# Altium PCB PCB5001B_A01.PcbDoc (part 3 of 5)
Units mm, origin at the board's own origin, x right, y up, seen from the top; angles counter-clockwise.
Board outline 115 x 60 mm, 6 copper layers (Top Layer, GND Layer 2, Signal Layer 3, Signal Layer 4, VCC Layer 5, Bottom Layer), stack 1.555 mm thick; 370 components, 274 nets, 1305 pads, 1129 vias.
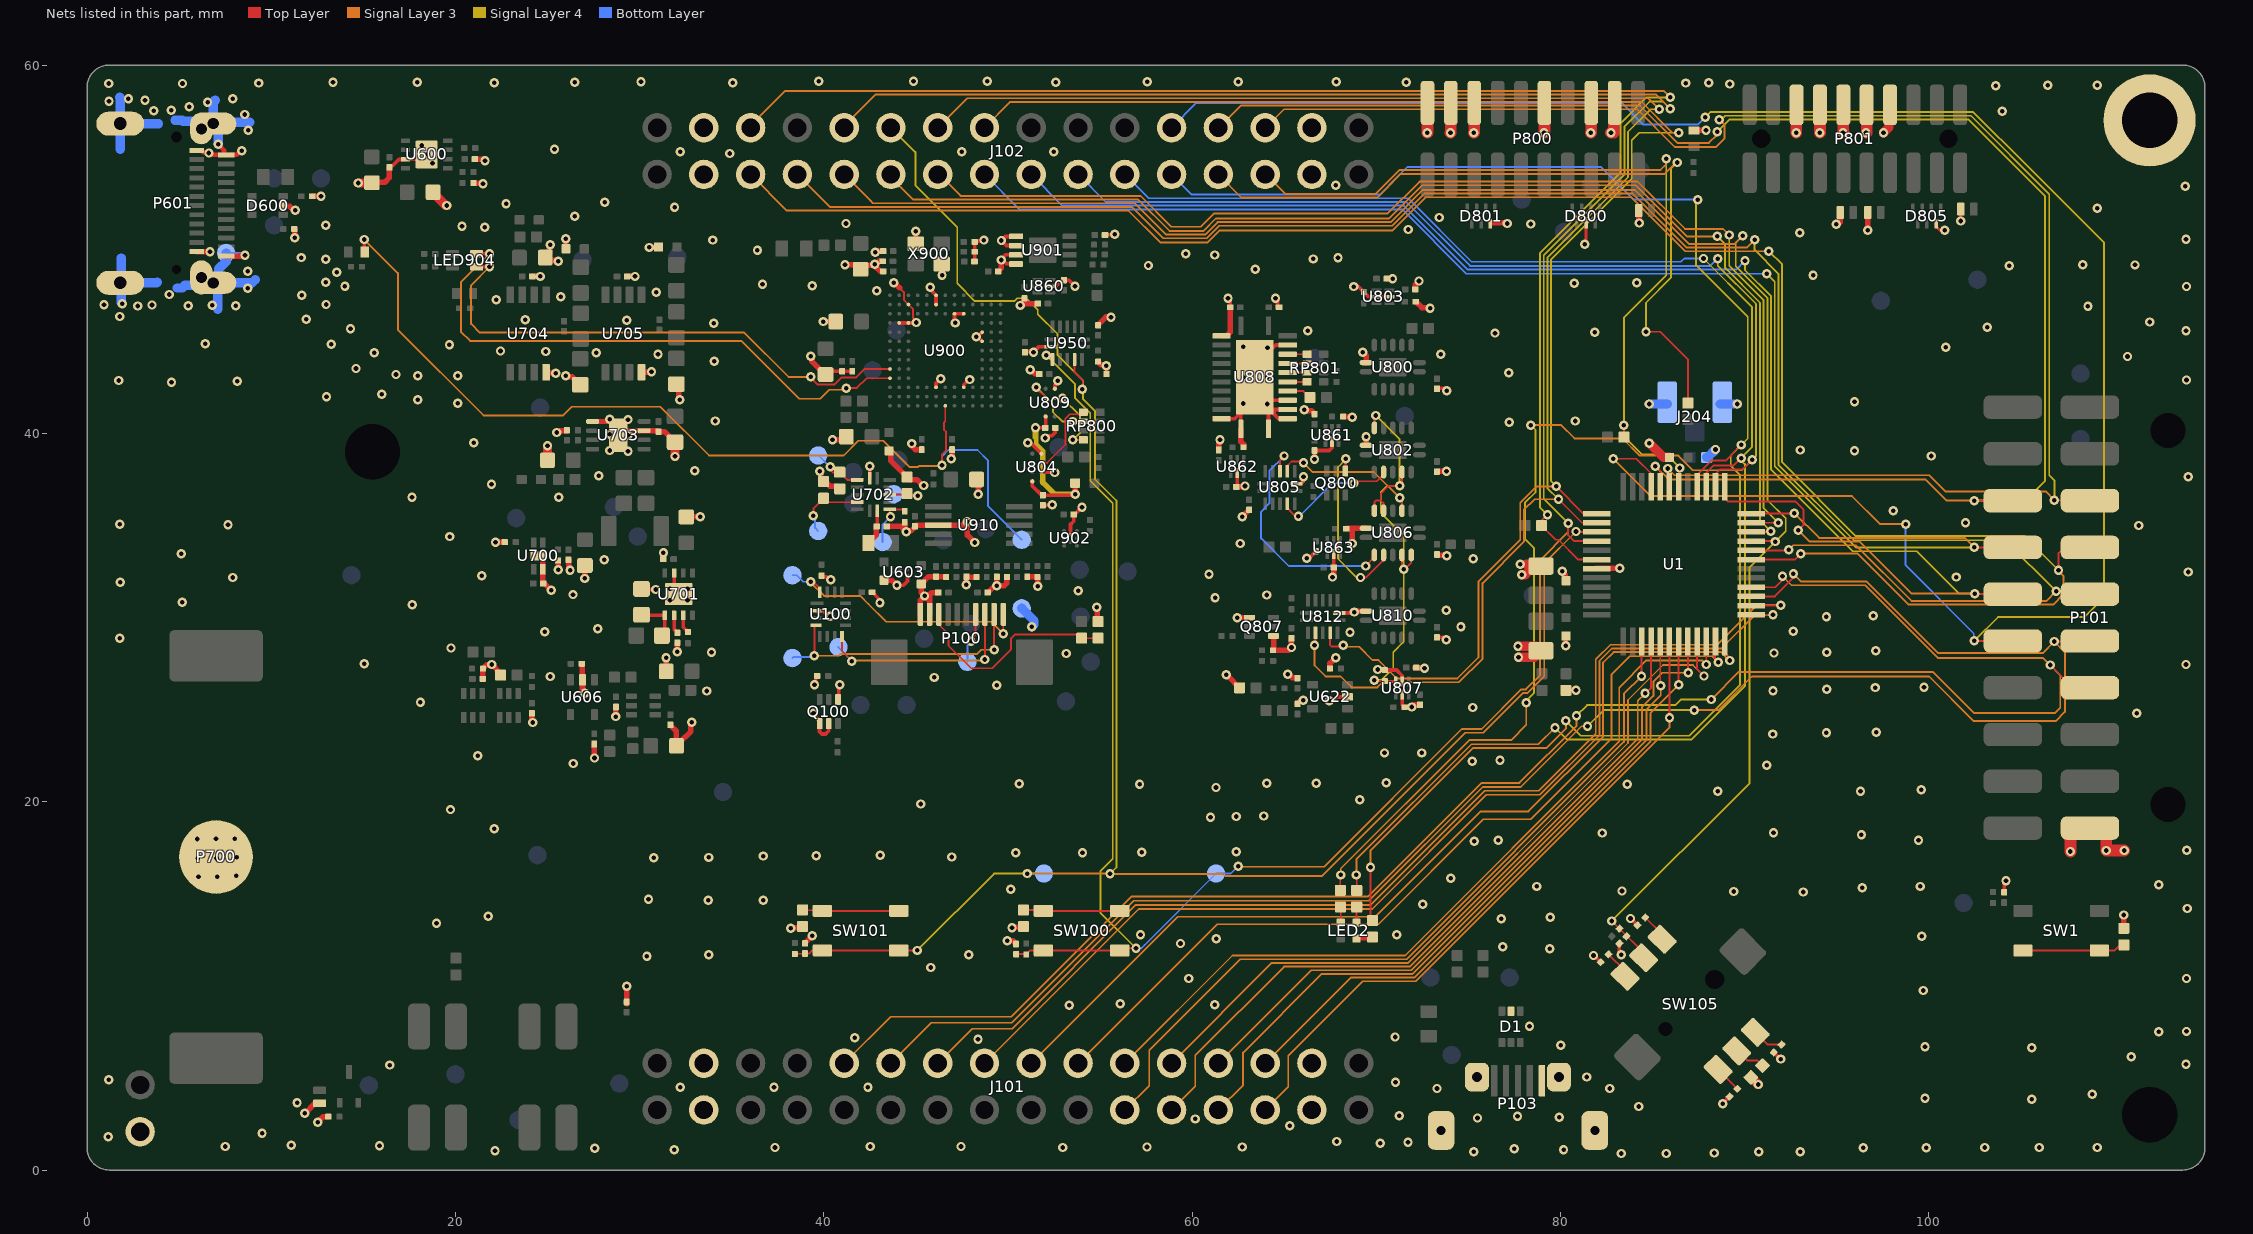
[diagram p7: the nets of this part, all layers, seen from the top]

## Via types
v1: diameter 0.508, hole 0.25, Top Layer to Bottom Layer, tented both sides, 1129 vias

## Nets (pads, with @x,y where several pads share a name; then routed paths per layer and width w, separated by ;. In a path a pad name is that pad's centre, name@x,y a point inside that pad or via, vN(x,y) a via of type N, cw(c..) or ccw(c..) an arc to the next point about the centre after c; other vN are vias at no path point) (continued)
EXP_HEADER7: J101.10 P101.7 U1.28 | length 100
  Top Layer w0.1: U1.28@90.375,31.65 91.677,31.65 92.075,32.048 92.075,32.247 v1(92.063,32.247) ; v1(106.6,27.425) 107.835,26.19 P101.7@108.76,26.19
  Signal Layer 3 w0.1: J101.10@41.11,5.802 41.128,5.82 43.633,8.325 50.175,8.325 56.7,14.85 69.55,14.85 75.725,21.025 77.775,21.025 80.879,24.129 80.879,24.671 v1(80.875,24.675) ; v1(88.2,25.55) 89.7,27.05 100.225,27.05 102.45,24.825 106.875,24.825 107.15,25.1 107.15,26.875 v1(106.6,27.425) 106.225,27.8 100.509,27.8 96.552,31.757 92.553,31.757 v1(92.063,32.247)
  Signal Layer 4 w0.1: v1(80.875,24.675) 81.45,25.25 86.25,25.25 86.55,25.55 v1(88.2,25.55)
EXP_HEADER9: J101.12 P101.9 U1.27 | length 98.8
  Top Layer w0.1: U1.27@90.375,31.15 91.65,31.15 92.657,32.157 v1(92.657,32.375) ; v1(106.825,28.7) 108.73,28.7 P101.9@108.76,28.73
  Signal Layer 3 w0.1: J101.12@43.65,5.802 45.848,8 50.2,8 56.825,14.625 69.608,14.625 75.783,20.8 77.85,20.8 81.15,24.1 v1(81.475,24.1) ; v1(87.275,24.975) 88.575,24.975 90.4,26.8 100.025,26.8 102.45,24.375 106.9,24.375 107.4,24.875 107.4,28.125 v1(106.825,28.7) 106.2,28.075 100.517,28.075 96.635,31.957 93.075,31.957 v1(92.657,32.375)
  Signal Layer 4 w0.1: v1(81.475,24.1) 82.35,24.975 v1(87.275,24.975)
EXP_HEADER10: J102.24 P101.10 U1.45 | length 112.6
  Top Layer w0.1: v1(82.875,38.625) 84.125,38.625 84.925,37.825 U1.45@84.925,37.1 ; v1(102.482,28.733) 104.567,28.733 P101.10@104.57,28.73
  Signal Layer 3 w0.1: v1(82.875,38.625) 84.9,36.6 95.837,36.6 97.362,35.075 v1(98.75,35.075)
  Signal Layer 4 w0.1: v1(87.875,57.175) 88.15,57.45 102.425,57.45 105.35,54.525 109.525,50.35 109.525,31.1 108.45,30.025 103.765,30.025 102.482,28.742 v1(102.482,28.733)
  Bottom Layer w0.1: J102.24@58.89,56.602 60.238,57.95 83.325,57.95 84.506,56.769 87.469,56.769 v1(87.875,57.175) ; v1(98.75,35.075) 98.75,32.838 102.452,29.137 102.452,28.763 v1(102.482,28.733)
EXP_HEADER11: J102.7 P101.11 U1.32 | length 106.5
  Top Layer w0.1: U1.32@90.375,33.65 92.375,33.65 v1(92.4,33.675) ; v1(106.919,31.424) 108.606,31.424 P101.11@108.76,31.27
  Signal Layer 3 w0.1: J102.7@38.57,54.062 40.332,52.3 56.725,52.3 58.425,50.6 60.792,50.6 61.467,51.275 70.867,51.275 72.617,53.025 83.932,53.025 86.864,50.093 90.118,50.093 v1(90.55,50.525) ; v1(92.4,33.675) 92.65,33.925 96.05,33.925 99.068,30.907 106.401,30.907 v1@106.912,31.418
  Signal Layer 4 w0.1: v1(90.55,50.525) 90.55,49.966 91.841,48.675 91.841,38.309 95.947,34.203 104.14,34.203 v1(106.919,31.424)
EXP_HEADER12: J102.17 P101.12 U1.37 | length 86.5
  Top Layer w0.1: U1.37@88.925,37.1 88.925,36.5 89.125,36.3 92.775,36.3 93.2,35.875 93.2,35.025 v1(92.925,34.75) ; v1(102.5,31.3) 102.526,31.274 104.566,31.274 P101.12@104.57,31.27
  Signal Layer 3 w0.1: v1(92.925,34.75) 93.55,34.125 96.25,34.125 99.075,31.3 v1(102.5,31.3)
  Signal Layer 4 w0.1: v1(90.025,49.375) 90.025,48.875 91.441,47.459 91.441,38.034 95.875,33.6 99.35,33.6 101.65,31.3 v1(102.5,31.3) v1@102.4,31.4
  Bottom Layer w0.1: J102.17@51.27,54.062 52.964,52.368 71.507,52.368 74.975,48.9 89.55,48.9 v1(90.025,49.375)
EXP_HEADER13: J102.5 P101.13 U1.31 | length 111
  Top Layer w0.1: U1.31@90.375,33.15 92.725,33.15 v1(93.05,33.475) ; v1(107.05,32.575) 107.05,33.5 107.41,33.86 P101.13@108.8,33.86
  Signal Layer 3 w0.1: J102.5@36.03,54.062 37.992,52.1 56.55,52.1 58.275,50.375 60.85,50.375 61.5,51.025 70.9,51.025 72.7,52.825 83.85,52.825 86.782,49.893 91.318,49.893 v1(91.325,49.9) ; v1(93.05,33.475) 96.15,33.475 98.918,30.707 106.757,30.707 107.318,31.268 107.318,32.272 107.05,32.539 v1(107.05,32.575)
  Signal Layer 4 w0.1: v1(91.325,49.9) 92.041,49.184 92.041,38.434 96.05,34.425 105.2,34.425 v1(107.05,32.575)
EXP_HEADER14: J102.15 P101.14 U1.36 | length 83
  Top Layer w0.1: U1.36@90.375,35.65 92.675,35.65 v1(92.7,35.675) ; v1(102.47,33.81) P101.14@104.57,33.81
  Signal Layer 3 w0.1: J102.15@48.73,54.062 J102.15@48.756,54.062 ; v1(92.7,35.675) 94.05,34.325 101.955,34.325 v1(102.47,33.81)
  Signal Layer 4 w0.1: v1(91.212,48.663) 91.641,48.234 91.641,38.209 96.04,33.81 v1(102.47,33.81)
  Bottom Layer w0.1: J102.15@48.73,54.062 50.624,52.168 71.407,52.168 74.9,48.675 91.2,48.675 v1(91.212,48.663)
EXP_HEADER15: J102.28 P101.15 U1.43 | length 88.8
  Top Layer w0.1: v1(85.835,38.096) 85.835,37.19 U1.43@85.925,37.1 ; v1(106.825,36.375) 107.941,36.375 107.966,36.4 P101.15@108.8,36.4
  Signal Layer 3 w0.1: J102.28@63.97,56.602 63.996,56.602 64.994,57.6 84.175,57.6 86.225,55.55 88.45,55.55 88.918,56.018 88.918,56.751 v1(88.631,57.037) ; v1(85.835,38.096) 85.835,38.09 86.2,37.725 100.025,37.725 100.9,36.85 106.35,36.85 v1(106.825,36.375)
  Signal Layer 4 w0.1: v1(88.631,57.037) 88.742,57.037 88.955,57.25 102.3,57.25 106.55,53 106.55,45.767 106.55,37.725 106.825,37.45 v1(106.825,36.375)
EXP_HEADER16: J102.26 P101.16 U1.44 | length 89.8
  Top Layer w0.1: v1(85.15,38.225) 85.169,38.225 85.425,37.969 U1.44@85.425,37.1 ; v1(102.47,36.35) P101.16@104.57,36.35
  Signal Layer 3 w0.1: J102.26@61.43,56.602 61.456,56.602 62.654,57.8 84.325,57.8 86.35,55.775 88.069,55.775 88.525,56.231 v1(88.525,56.375) ; v1(85.15,38.225) 85.875,37.5 99.825,37.5 100.975,36.35 v1(102.47,36.35)
  Signal Layer 4 w0.1: v1(88.525,56.375) 89.2,57.05 102.15,57.05 106.325,52.875 106.325,37.425 105.25,36.35 v1(102.47,36.35)
GND: C1.2 C2.2 C3.2 C4.2 C8.2 C102.2 C103.2 C104.2 C106.2 C113.2 C143.2 C144.2 C600.2 C602.2 C607.2 C608.2 C609.2 C610.2 C611.2 C621.2 C625.2 C632.2 C635.2 C638.2 C641.2 C652.2 C653.2 C655.2 C660.2 C673.2 C674.2 C700.2 C701.2 C702.2 C703.2 C705.2 C706.2 C707.2 C708.2 C714.2 C720.2 C724.2 C728.2 C729.2 C730.2 C731.2 C732.2 C800.2 C803.2 C804.2 C805.2 C806.2 C807.2 C808.2 C809.2 C810.2 C827.2 C828.2 C860.2 C861.2 C862.2 C863.2 C864.2 C865.2 C866.2 C867.2 C868.2 C869.2 C870.2 C900.2 C901.2 C902.2 C903.2 C904.2 C905.2 C906.2 C907.2 C908.2 C909.2 C910.2 C911.2 C914.2 C921.2 C922.2 C924.2 C925.2 C926.2 C927.2 C950.2 C951.2 D1.2 D600.2 D703.2 D800.6 D801.7 D805.7 D806.2 D807.2 D808.2 D809.2 J101.3 J101.4 J101.29 J101.30 J102.3 J102.4 J102.29 J102.30 J204.2 J204.3 LED900.2 M1.1 P100.1 P100.2 P101.1 P103.5 P103.6 P103.7 P103.8 P103.9 P601.25@1.8,56.82 P601.26@1.8,48.18 P601.27@6.2,56.525 P601.27@6.85,56.82 P601.28@6.2,48.475 P601.28@6.85,48.18 P601.A1 P601.A12 P601.B1 P601.B12 P700.2 P800.3 P800.5 P800.9 P800.15 P800.17 P800.19 P801.7 P801.9 P801.11 P801.13 P801.15 Q100.1 Q100.4 Q100.5 Q807.1 Q807.4 R7.1 R104.2 R105.2 R113.1 R121.1 R124.1 R125.1 R126.1 R127.1 R140.1 R141.1 R146.1 R220.1 R602.1 R620.1 R621.1 R623.1 R628.2 R631.1 R634.1 R637.1 R640.1 R674.2 R688.2 R691.2 R703.1 R705.1 R706.1 R707.1 R708.1 R718.1 R760.1 R763.1 R767.1 R771.1 R792.1 R807.2 R808.2 R814.1 R817.1 R839.1 R850.1 R851.1 R852.1 R853.1 R930.2 R931.2 R950.2 R981.2 ST701.1 TPJ614.1 TPJ913.1 U1.7 U100.2 U600.3 U600.9 U603.A1 U606.2 U622.2 U700.2 U700.5 U701.3 U701.9 U702.7 U703.3 U703.5 U703.9 U704.4 U705.4 U800.7 U802.7 U803.2 U803.5 U804.B1 U804.D1 U805.7 U806.7 U807.2 U807.5 U808.2 U808.11 U808.12 U808.13 U808.14 U808.15 U808.16 U808.22 U808.25 U809.D1 U810.7 U812.7 U860.2 U861.2 U862.2 U863.2 U900.C5 U900.C8 U900.H3 U900.J3 U900.K11 U900.K12 U900.L5 U900.L6 U900.M8 U900.M11 U900.N8 U901.1 U901.2 U901.3 U901.4 U902.B2 U910.3 U950.7 X900.2 X900.4 | length 231.2
  Top Layer w0.1: 44.125,47.9 44.35,47.675 44.35,47.25 U900.M11@44.6,47 44.788,46.813 44.85,46.75 44.85,46.275 v1@45.025,46.1
  Top Layer w0.15: v1(81.325,50.275) 81.4,50.35 D800.6@81.4,51.385 ; D805.7@100.4,51.385 100.4,51.25 100.6,51.05 v1@101.05,51.05
  Top Layer w0.2: C600.2@16.417,54.451 16.417,54.471 16.477,54.531 16.581,54.531 16.922,54.872 17.257,54.872 U600.3@17.282,54.897 U600.9@18.182,54.897 ; R703.1@30.105,31.556 30.135,31.525 v1(30.875,31.525) ; U701.9@31.725,31.575 31.875,31.725 U701.3@31.875,32.425 ; v1(39.446,24.8) 39.446,24.719 39.775,24.39 Q100.4@39.775,24.24 39.775,23.8 39.9,23.675 40.1,23.675 40.275,23.85 Q100.5@40.275,24.24 ; v1(39.498,26.353) 39.498,26.437 39.572,26.511 39.572,26.772 39.632,26.832 R141.1@39.642,26.832 ; U100.2@39.59,30.375 39.956,30.375 40.261,30.07 v1(40.344,30.07) ; R140.1@39.888,32.275 39.888,32.265 39.948,32.205 40.158,32.205 40.307,32.057 v1(40.39,32.057) ; C907.2@40.1,43.2 40.275,43.375 C924.2@41,43.375 C925.2@41.55,43.375 ; Q100.1@40.775,25.54 40.818,25.583 40.818,26.306 v1(40.862,26.35) ; U702.7@42.5,37.56 v1(42.5,38.225) v1@42.65,38.225 ; C104.2@42.623,31.374 42.643,31.374 42.993,31.024 42.993,30.863 v1(43.052,30.804) ; v1(43.975,31.75) 44.325,31.75 44.55,31.975 U603.A1@44.55,32.25 ; U900.K12@44.1,46 U900.K11@44.6,46 45,46 v1(45.025,46.025) v1@45.025,46.1 ; v1@45.35,37.1 v1(45.425,37.175) ; v1(45.793,47.935) 45.793,47.802 46.095,47.5 U900.N8@46.1,47.5 U900.M8@46.1,47 ; U900.C8@46.1,42.5 46.1,42.725 v1(46.35,42.975) ; v1(47.15,46) 47.1,46.05 U900.L6@47.1,46.5 U900.L5@47.6,46.5 ; U900.C5@47.6,42.5 47.6,42.65 v1@47.875,42.925 ; C910.2@48.184,49.333 48.193,49.342 48.193,49.857 R930.2@48.201,49.865 ; R930.2@48.202,49.863 R930.2@48.201,49.865 ; v1@48.224,45.25 v1(48.275,45.25) 48.3,45.25 v1@48.325,45.275 ; U900.H3@48.6,45 v1@48.325,45.275 ; U900.J3@48.6,45.5 48.375,45.275 v1@48.325,45.275 ; v1(48.7,50.5) 48.65,50.45 48.25,50.45 R931.2@48.2,50.4 48.201,50.399 R930.2@48.201,49.865 ; v1@49.65,49.4 49.733,49.4 49.923,49.21 50.434,49.21 U901.4@50.445,49.2 ; v1@49.65,49.483 49.867,49.7 U901.3@50.445,49.7 ; U901.2@50.445,50.2 50.436,50.208 49.917,50.208 v1(49.65,50.475) 49.867,50.692 50.436,50.692 U901.1@50.445,50.7 ; C911.2@50.925,44.4 50.95,44.375 50.993,44.375 51.068,44.45 51.355,44.45 v1(51.392,44.413) ; v1@51.225,39.45 51.275,39.45 U804.D1@51.825,38.9 ; v1@51.4,44.45 51.413,44.45 51.663,44.7 U950.7@52.34,44.7 ; U804.B1@51.825,37.9 52.525,37.9 v1(52.55,37.875) ; C804.2@51.9,36.1 52.375,36.1 v1(52.4,36.125) ; v1(52.025,39.75) 52.15,39.875 52.4,39.875 52.575,40.05 C810.2@52.575,40.3 ; U860.2@52.3,48 52.625,48 52.95,48.325 C862.2@53.05,48.325 53.309,48.325 v1(53.645,47.989) ; U809.D1@52.55,42.425 52.556,42.431 52.556,42.63 52.709,42.784 v1(52.709,42.867) ; C862.2@53.05,48.305 C862.2@53.11,48.245 ; U902.B2@53.4,34.5 53.4,35.05 53.575,35.225 C914.2@53.575,35.55 ; C914.2@53.575,35.6 C914.2@53.575,35.55 ; v1(54.025,36) C914.2@53.575,35.55 ; C951.2@55.272,50.778 55.29,50.796 55.787,50.796 v1(55.805,50.814) ; R981.2@55.35,43.225 v1(55.35,43.679) ; U808.11@61.605,40.8 62.325,40.8 U808.25@62.65,41.125 ; v1(61.95,47.35) 62.075,47.225 C808.2@62.075,46.85 ; C860.2@62.4,37.1 62.45,37.15 U862.2@62.45,37.85 ; U808.12@62.65,40.255 U808.25@62.65,41.125 ; v1(62.775,41.625) 62.775,41.25 U808.25@62.65,41.125 ; v1(64.1,44.65) 64.4,44.65 64.55,44.8 U808.22@65.195,44.8 ; U808.13@64.15,40.255 64.15,41.3 64.2,41.3 64.45,41.05 ; v1(64.532,47.345) 64.532,47.275 64.645,47.162 64.645,46.91 64.705,46.85 C806.2@64.725,46.85 ; U808.14@65.195,40.8 64.7,40.8 64.45,41.05 ; U808.15@65.195,41.3 U808.25@64.375,41.3 ; U808.16@65.195,41.8 64.275,41.8 v1(64.075,41.6) U808.25@64.375,41.3 ; U805.7@65.66,37.27 65.92,37.27 66.025,37.375 66.025,37.625 v1(66.05,37.65) ; v1(66.225,33.225) 66.35,33.225 C867.2@66.725,33.6 ; v1(66.65,38.6) C864.2@66.65,39.075 67.45,39.075 67.6,39.225 U861.2@67.6,39.55 ; v1(67.45,25.475) 67.643,25.475 67.859,25.691 68.441,25.691 U622.2@68.45,25.7 ; C866.2@67.7,32.725 U863.2@67.7,33.45 ; U812.7@67.985,30.25 68.75,30.25 v1(68.8,30.3) ; C827.2@73.3,28.925 73.675,28.925 v1(73.8,28.8) ; C803.2@73.325,42.45 73.7,42.45 v1(73.825,42.325) ; v1@73.802,37.938 v1(73.816,37.951) ; v1(81.8,11.65) 81.826,11.65 R124.1@82.188,11.288 ; C106.2@83.206,12.306 83.206,11.794 v1(83.3,11.7) ; v1(83.807,13.657) 83.833,13.657 R127.1@84.195,13.295 ; v1(88.826,3.6) 88.826,3.626 R125.1@89.188,3.988 ; R126.1@91.588,6.388 91.95,6.026 v1(91.976,6.026) ; v1@101.749,51.534 D808.2@101.748,52.181 ; C8.2@104.1,15.075 104.1,15.6 v1(104.2,15.7) ; U808.25@64.375,41.3 64.45,41.225 64.45,41.05
  Top Layer w0.203: v1(68.775,47.975) 69.025,47.975 R807.2@69.325,47.675 69.575,47.425 U803.2@70.025,47.425 U803.5@70.725,47.425 ; v1(70.077,27.182) 70.093,27.166 70.459,27.166 R808.2@70.475,27.15 71.1,27.15 71.413,26.837 U807.2@71.413,26.525 ; U807.5@71.413,25.825 71.413,25.249 R814.1@71.532,25.13
  Top Layer w0.25: P601.B12@5.95,55.375 5.96,55.365 6.225,55.365 6.313,55.277 6.566,55.277 v1(6.615,55.227) ; v1@6.658,55.178 6.735,55.178 6.777,55.135 P601.A1@7.432,55.135 ; v1(7.128,55.71) 7.128,55.689 7.432,55.385 P601.A1@7.432,55.135 ; v1(8.398,55.347) 8.328,55.347 8.116,55.135 7.56,55.135 P601.A1@7.55,55.125 ; U703.5@27.45,40.65 v1@28.25,40.65 ; P601.A1@7.432,55.135 7.54,55.135 P601.A1@7.55,55.125 ; P601.A1@7.432,55.135 7.442,55.125 P601.A1@7.55,55.125
  Top Layer w0.254: v1(80.1,32.525) 80.3,32.325 C2.2@80.3,32 ; v1(80.3,28.475) C4.2@80.3,29
  Top Layer w0.3: P601.B1@5.95,49.875 v1(6.675,49.875) ; P601.A12@7.55,49.625 8.25,49.625 8.26,49.635 8.535,49.635 v1(8.575,49.675) ; D600.2@10.647,52.374 10.684,52.336 10.993,52.336 11.207,52.122 v1(11.298,52.122) ; R621.1@11.25,51.1 11.252,51.1 11.262,51.09 11.262,50.637 v1(11.275,50.625) ; R620.1@12.224,52.88 12.226,52.878 12.697,52.878 v1(12.7,52.875) ; C611.2@15.525,53.55 15.614,53.639 16.164,53.639 16.417,53.892 C600.2@16.417,54.451 ; R602.1@20.982,53.597 20.982,53.587 20.992,53.577 21.472,53.577 v1(21.498,53.552) ; C602.2@21.057,54.897 21.507,54.897 v1(21.607,54.797) ; C610.2@21.475,26.675 21.475,27.2 R623.1@21.5,27.225 21.725,27.45 v1(21.975,27.45) 22.45,26.975 R628.2@22.45,26.875 ; v1(22.175,34.1) v1(22.175,34.1) 22.678,34.099 R763.1@22.679,34.098 ; C621.2@24.15,24.8 24.15,24.35 v1(24.2,24.3) ; U700.5@24.5,33.35 24.65,33.35 24.75,33.25 U700.2@24.75,32.625 24.75,31.875 C708.2@24.775,31.85 24.825,31.85 v1(25.2,31.475) ; v1(25.5,40.05) 25.556,40.05 25.651,40.145 26.04,40.145 26.05,40.155 C728.2@26.05,40.175 ; R760.1@25.573,33.103 R760.1@25.573,33.103 v1(25.575,32.6) v1(25.575,32.6) ; C701.2@26.134,33.137 26.144,33.127 26.144,32.713 26.225,32.631 v1(26.225,32.575) ; R674.2@26.86,27.49 26.87,27.49 26.88,27.48 26.88,26.645 U606.2@26.9,26.625 26.9,26.025 v1(27.025,25.9) ; v1(27.025,32.125) 27.029,32.129 27.029,32.821 C700.2@27.033,32.825 ; C660.2@27.537,23.135 27.544,23.128 27.544,22.381 v1(27.55,22.375) ; v1@28.25,40.65 v1(28.375,40.775) ; v1(28.7,24.625) 28.706,24.631 28.706,25.14 C674.2@28.713,25.147 ; U703.9@28.85,39.9 U703.9@29.1,40.15 ; v1(29.373,40.753) 29.334,40.713 29.334,40.65 29.2,40.65 29.1,40.55 U703.9@29.1,40.15 ; C702.2@31.295,33.171 v1(31.295,33.521) ; v1(31.438,27.822) 31.443,27.817 31.443,27.085 C625.2@31.448,27.08 ; C673.2@31.685,24.145 32.004,23.826 C655.2@32.004,23.061 ; R718.1@31.925,39.525 31.35,40.1 C729.2@31.025,40.1 30.975,40.15 U703.3@30.25,40.15 U703.9@29.1,40.15 ; C655.2@32.004,23.036 C655.2@32.004,23.061 ; v1(32.05,28.15) C705.2@32.05,28.629 ; C703.2@32.535,35.461 32.542,35.468 33.293,35.468 v1(33.3,35.475) ; v1(32.826,24.318) 32.787,24.278 32.787,23.819 32.493,23.526 32.468,23.526 C655.2@32.004,23.061 ; v1@38.15,13.15 38.165,13.165 38.79,13.165 R105.2@38.85,13.225 ; v1(38.2,13.125) v1@38.225,13.15 ; C103.2@38.986,12.306 38.986,12.326 39.373,12.713 v1(39.382,12.713) ; v1(39.304,44.196) 39.343,44.156 39.343,43.932 40.075,43.2 C907.2@40.1,43.2 ; v1(39.793,37.95) 39.793,37.894 39.843,37.844 39.843,37.529 R705.1@39.993,37.379 ; v1(39.975,46.075) C900.2@40.65,46.075 ; R705.1@40.125,37.35 40.125,37.247 40.143,37.229 40.246,37.229 40.331,37.144 40.72,37.144 R706.1@40.87,36.994 ; v1(40.475,39.65) 41.05,39.65 C902.2@41.225,39.825 ; v1(41.156,49.165) 41.756,49.165 C903.2@42.006,48.915 ; C903.2@42.1,49 42.229,49.129 42.723,49.129 v1(42.777,49.183) ; v1(42.804,49.833) 42.861,49.833 42.914,49.886 43.213,49.886 C906.2@43.223,49.896 ; C905.2@43.21,49.352 43.2,49.342 42.992,49.342 42.834,49.183 v1(42.777,49.183) ; C904.2@43.223,48.802 43.213,48.812 43.057,48.812 42.817,49.052 42.817,49.143 v1(42.777,49.183) ; C609.2@43.275,32.025 43.7,32.025 v1(43.975,31.75) ; C707.2@43.425,34.95 44.193,34.95 v1@44.396,34.747 ; C901.2@43.55,39.05 43.65,38.95 43.65,38.512 R707.1@44.523,37.639 44.673,37.489 45.054,37.489 45.369,37.175 v1(45.425,37.175) ; v1(43.8,48.182) 43.843,48.182 44.125,47.9 ; R708.1@44.4,35.175 44.4,35.159 44.396,35.155 v1@44.396,34.747 ; v1(44.476,34.667) v1@44.396,34.747 ; v1@44.5,34.6 44.5,34.635 44.572,34.707 44.727,34.707 44.95,34.93 C922.2@44.95,34.95 ; v1(44.775,39.45) 44.775,39.325 44.975,39.125 C927.2@45.325,39.125 ; C922.2@44.94,34.94 C922.2@44.95,34.95 ; X900.4@45,50.3 v1(45,50.975) ; P100.1@45.25,30.175 45.25,30.95 v1(45.475,31.175) ; P100.2@45.75,30.175 45.75,30.9 ; C143.2@46.224,31.364 46.214,31.354 45.854,31.354 45.75,31.25 ; X900.2@46.4,49.2 46.4,48.6 46.421,48.579 v1(46.425,48.582) ; R637.1@46.65,32.2 46.625,32.225 C638.2@46.1,32.225 45.7,32.225 C608.2@45.3,31.825 45.3,31.35 v1(45.475,31.175) ; v1@46.975,38.625 C926.2@46.975,39.125 ; v1(47.742,31.782) v1@47.746,31.786 ; v1@47.782,31.822 v1@47.746,31.786 ; v1@47.825,35.225 v1(47.8,35.2) ; v1(48.2,34.075) 47.8,34.475 v1(47.8,35.2) ; R640.1@48.29,32.18 48.29,32.19 R640.1@48.3,32.2 47.775,32.2 C641.2@47.75,32.225 47.746,32.221 v1@47.746,31.786 ; C921.2@48.3,37.5 48.4,37.4 v1(48.4,36.7) ; C144.2@48.9,31.368 48.92,31.368 49.236,31.685 49.36,31.685 v1(49.4,31.725) ; C635.2@49.4,32.225 v1(49.4,31.725) ; C908.2@49.475,48.8 49.65,48.975 49.65,49.4 v1(49.634,49.416) ; R634.1@49.95,32.2 49.95,31.875 49.8,31.725 v1(49.4,31.725) ; v1(49.975,12.45) 50.275,12.45 C102.2@50.45,12.275 ; v1@50.225,13.125 50.285,13.185 50.812,13.185 R104.2@50.847,13.22 ; R850.1@50.9,47.342 50.89,47.332 50.89,47.221 50.675,47.006 v1(50.675,46.95) 50.731,46.95 50.831,47.05 C863.2@51.625,47.05 ; C632.2@51.05,32.225 51.575,32.225 R631.1@51.6,32.2 51.625,32.175 v1(51.625,31.7) ; v1(51.214,43.449) 51.27,43.449 51.484,43.234 51.695,43.234 C909.2@51.705,43.224 ; v1(54.834,30.559) 54.856,30.537 54.856,29.793 R146.1@54.877,29.772 ; R950.2@54.9,43.9 54.9,43.89 55.071,43.719 55.311,43.719 v1(55.35,43.679) ; C950.2@54.9,45.875 54.91,45.885 54.91,45.905 55.328,46.323 55.577,46.323 v1(55.6,46.3) ; C861.2@61.45,39.1 61.46,39.11 61.46,39.536 61.518,39.594 v1(61.518,39.65) ; U808.2@61.605,45.3 61.875,45.3 62.075,45.5 C808.2@62.075,46.85 ; v1(61.853,26.903) 61.975,26.903 61.975,26.789 R691.2@62.577,26.187 ; C860.2@62.4,37.1 62.773,37.1 62.819,37.145 v1(62.875,37.145) ; v1(62.45,30) Q807.4@63.125,30 ; U808.12@62.65,40.255 62.65,39.55 62.8,39.4 R852.1@62.8,39.25 ; v1(62.725,35.475) C800.2@63.1,35.85 ; Q807.1@64.425,29 64.425,28.25 R839.1@64.4,28.225 65.25,28.225 v1(65.4,28.375) C828.2@65.4,28.875 ; v1(65.2,26.921) 65.256,26.921 65.432,26.745 65.71,26.745 65.72,26.735 C653.2@65.72,26.715 ; C652.2@65.725,25.311 65.725,25.331 65.979,25.585 v1(66.048,25.516) ; v1(66.1,41.282) 66.138,41.244 66.476,41.244 C865.2@66.64,41.08 ; R688.2@67.486,27.233 67.486,27.511 v1(67.8,27.825) ; v1(67.625,32.2) 67.7,32.275 C866.2@67.7,32.725 ; R851.1@68.2,40.912 68.21,40.902 68.673,40.902 v1(68.7,40.875) ; R853.1@68.375,34.825 68.4,34.85 68.678,34.85 ; v1(68.7,34.025) 68.7,34.822 68.675,34.847 68.678,34.85 ; v1(68.8,30.3) 68.85,30.35 U810.7@69.45,30.35 ; v1(69.275,44.4) 69.45,44.225 U800.7@69.45,43.85 ; U806.7@69.45,34.85 68.678,34.85 ; U802.7@69.45,39.35 v1(69.45,39.825) ; C809.2@73.3,33.425 73.3,33.405 73.31,33.395 73.724,33.395 73.769,33.35 v1(73.825,33.35) ; C805.2@73.3,37.925 73.3,37.928 73.31,37.938 73.788,37.938 v1@73.811,37.961 ; v1(73.825,42.325) v1@73.881,42.325 ; D801.7@76.255,51.449 77.076,51.449 v1(77.125,51.4) ; D809.2@84.25,52.1 84.271,52.079 84.271,51.446 v1(84.293,51.425) ; LED900.2@87.25,56.45 87.26,56.46 87.898,56.46 v1(87.908,56.47) ; v1(94.975,51.35) 95.075,51.35 95.2,51.475 D806.2@95.2,52 ; v1(96.692,51.031) 96.696,51.035 96.696,51.996 D807.2@96.7,52 ; R7.1@110.6,13.125 v1(110.6,13.85) ; C922.2@44.95,34.95 45.025,35.025 U910.3@46.225,35.025 47.625,35.025 v1(47.8,35.2) ; v1(45.475,31.175) 45.55,31.25 45.75,31.25 ; v1(45.475,31.175) 45.75,30.9 ; 45.75,30.9 45.75,31.25
  Top Layer w0.305: v1(11.825,3.075) 12.375,3.625 D703.2@12.625,3.625 ; v1(12.525,2.6) 12.825,2.9 R792.1@13.1,2.9 ; C730.2@24.175,48.525 v1(24.6,48.525) ; C731.2@24.875,49.55 25.111,49.786 25.111,50.211 v1(25.15,50.25) ; C731.2@24.914,49.511 25.036,49.389 25.536,49.389 v1(25.575,49.35) ; U704.4@24.925,43.32 24.947,43.297 25.428,43.297 v1(25.45,43.275) ; v1(26,43.125) 26.039,43.086 26.314,43.086 26.75,42.65 R767.1@26.775,42.65 ; C720.2@26,50.025 v1(26,50.575) ; C706.2@29.3,9.025 v1(29.3,9.975) ; C732.2@29.325,48.525 v1(29.75,48.525) ; U705.4@30.1,43.32 30.62,43.32 v1(30.65,43.35) ; v1(30.525,50.1) 31,50.1 C724.2@31.025,50.125 ; R771.1@32,42.675 32.136,42.539 32.136,41.864 v1(32.175,41.825) ; C869.2@70.569,48.403 v1(70.889,48.403) ; R814.1@71.532,25.13 71.538,25.136 71.838,25.136 71.845,25.143 v1(71.932,25.143) ; v1@71.932,25.13 72.066,25.264 C868.2@72.376,25.264 ; C870.2@72.089,27.284 C870.2@72.175,27.284 72.591,27.284 v1(72.625,27.25) v1@72.601,27.226 ; C807.2@72.125,47.825 72.125,48.075 v1(72.325,48.275) ; R817.1@72.15,47.15 72.16,47.15 72.478,46.832 72.886,46.832 v1(72.925,46.793) ; R121.1@80.325,26.05 v1(80.85,26.05) ; U1.7@81.954,32.675 v1(83.225,32.675)
  Top Layer w0.5: v1(14.721,53.599) 14.722,53.601 15.451,53.601 C611.2@15.465,53.614 ; C607.2@18.782,53.097 18.782,53.072 19.478,52.377 19.523,52.377 v1(19.525,52.375) ; C714.2@25,38.55 v1(25,39.325) ; v1(31.925,38.75) R718.1@31.925,39.525 ; R113.1@90.342,5.037 90.351,5.037 90.743,4.645 v1(90.745,4.645) ; v1(97.55,56.325) 97.85,56.625 97.85,57.786 P801.7@97.905,57.841
  Top Layer w0.508: v1(77.7,28.45) 78.675,28.45 78.925,28.2 C3.2@78.95,28.2 78.6,27.85 v1(77.725,27.85) ; v1(77.9,32.325) 78.1,32.325 C1.2@78.375,32.6 ; 78.162,32.9 78.263,32.8 C1.2@78.95,32.8 ; v1(84.825,39.475) 85.6,38.7 C113.2@85.925,38.7
  Top Layer w0.635: v1(72.765,56.325) 72.785,56.345 P800.19@72.785,57.95 ; v1(74.035,56.325) 74.055,56.345 P800.17@74.055,57.95 ; v1(75.305,56.325) 75.325,56.345 P800.15@75.325,57.95 ; v1(79.115,56.325) 79.135,56.345 P800.9@79.135,57.95 ; v1(81.655,56.325) 81.675,56.345 P800.5@81.675,57.95 ; v1(82.75,56.325) 82.882,56.325 82.893,56.335 82.893,57.897 P800.3@82.945,57.95 ; v1(92.811,56.325) 92.811,57.828 P801.15@92.825,57.841 ; v1(94.08,56.325) 94.105,56.325 94.095,56.335 P801.13@94.095,57.841 ; v1(95.35,56.325) 95.375,56.325 95.365,56.335 P801.11@95.365,57.841 ; v1@96.635,56.335 P801.9@96.635,57.841 ; v1(107.7,17.3) 107.7,18.253 108.018,18.57 P101.1@108.76,18.57 109.705,18.57 109.65,18.515 v1(109.65,17.35) v1(110.625,17.35)
  Bottom Layer w0.3: TPJ614.1@7.6,49.725 7.61,49.715 8.535,49.715 v1(8.575,49.675)
  Bottom Layer w0.5: TPJ913.1@50.751,30.501 51.425,29.828 51.425,29.625 v1(51.3,29.5)
  Bottom Layer w0.508: 1.775,58.25 1.8,58.225 P601.25@1.8,56.82 ; 1.8,55.425 P601.25@1.8,56.82 ; v1@1.85,47.1 1.85,48.13 P601.26@1.8,48.18 ; 1.85,49.525 1.85,48.23 P601.26@1.8,48.18 ; 3.8,48.2 3.78,48.18 P601.26@1.8,48.18 ; 3.875,56.825 3.87,56.82 P601.25@1.8,56.82 ; 4.775,57 5.158,57 5.205,56.952 6.718,56.952 P601.27@6.85,56.82 ; 4.9,47.9 5.162,47.9 5.31,48.048 6.718,48.048 P601.28@6.85,48.18 P601.28@7.136,48.18 ; 6.95,58.1 6.85,58 P601.27@6.85,56.82 ; 7.1,46.75 P601.28@7.1,47.93 ; v1@7.125,55.725 7.125,56.545 P601.27@6.85,56.82 ; TPJ614.1@7.55,49.8 7.55,49.339 7.136,48.925 P601.28@7.136,48.18 ; 8.825,56.9 6.93,56.9 P601.27@6.85,56.82 ; 9.125,48.35 8.955,48.18 P601.28@7.136,48.18 ; v1(84.825,41.6) J204.2@85.8,41.6 ; R220.1@87.95,38.7 88,38.7 v1(88.425,39.125) ; J204.3@88.675,41.6 v1(89.6,41.6)
  other v1: 83.3,0.9 85.75,0.9 88.35,0.925 75.289,0.993 90.775,1 93.025,1 22.15,1.05 31.877,1.101 80.175,1.1 77.5,1.15 27.575,1.175 96.452,1.201 99.877,1.201 37.352,1.226 52.975,1.225 103.052,1.226 106.002,1.226 109.152,1.226 57.552,1.251 62.727,1.251 7.502,1.276 42.527,1.276 47.452,1.276 15.877,1.326 11.077,1.351 70.225,1.45 71.725,1.5 67.85,1.55 1.152,1.801 9.5,2 65.3,2.4 60.175,2.775 75.5,2.823 79.95,2.875 77.675,2.925 71.25,2.95 84.25,3.45 11.4,3.65 105.6,3.85 99.8,3.9 108.875,4.125 73.3,4.425 82.675,4.425 32.2,4.5 37.3,4.5 42.4,4.5 71.05,4.775 1.177,4.901 81.425,5.05 16.425,5.7 113.977,5.751 111,6.15 105.6,6.65 99.8,6.7 80.025,6.775 48.375,7.1 41.693,7.177 71.025,7.225 112.5,7.5 114.002,7.526 78.325,7.8 53.325,8.95 61.225,8.975 56.1,9.025 99.7,9.75 59.822,10.403 114.002,10.401 45.807,10.999 30.4,11.6 33.75,11.7 47.875,11.7 79.425,12.025 76.875,12.125 59.375,12.3 61.319,12.563 99.625,12.7 57.2,12.782 71.125,12.775 50.225,13.15 18.975,13.4 76.8,13.65 79.45,13.725 21.775,13.775 114.052,14.201 72.525,14.425 33.725,14.65 36.725,14.65 30.482,14.699 93.2,15.1 89.425,15.125 83.35,15.15 50.157,15.254 96.4,15.325 78.725,15.4 99.55,15.4 112.5,15.5 74.05,15.85 6.05,15.925 7.075,15.925 8.1,15.975 6,16.925 7.025,16.925 30.775,16.95 8.125,16.975 33.75,16.975 46.95,17 36.725,17.05 39.6,17.075 43.075,17.1 50.425,17.225 54.05,17.225 57.275,17.25 62.4,17.275 114.025,17.375 75.325,17.85 76.625,17.9 99.45,17.9 5.975,17.975 7,18 8.025,18 96.35,18.2 82.275,18.3 91.575,18.325 22.107,18.524 61,19.15 62.4,19.2 63.9,19.225 19.732,19.574 45.275,19.875 69.1,20.1 88.55,20.575 96.3,20.575 99.6,20.65 61.3,20.775 57.15,20.95 83.625,20.95 50.625,20.975 64.05,21 66.75,21 70.55,21.025 91.214,21.975 26.4,22.075 75.225,22.2 76.725,22.25 21.207,22.499 70.45,22.65 72.475,22.65 91.525,23.675 94.45,23.75 97.15,23.775 111.3,24.8 75.252,25.12 18.1,25.4 33.652,26.011 91.55,26.025 94.475,26.1 97.1,26.2 99.75,26.225 49.398,26.329 45.998,26.75 25.157,26.799 113.977,27.451 15.05,27.5 53.175,28.05 91.6,28.075 33.907,28.124 94.475,28.125 97.125,28.2 19.757,28.349 1.775,28.875 68.575,29.2 24.857,29.224 92.65,29.25 27.732,29.399 74.602,29.495 94.45,30.05 97,30.1 73.807,30.4 17.657,30.699 5.157,30.824 31.65,30.95 32.6,30.95 61.25,31.075 64.05,31.225 26.382,31.249 53.825,31.45 31.65,31.575 32.6,31.575 1.8,31.925 7.907,32.174 101.5,32.2 21.432,32.274 60.923,32.354 114.102,32.476 77.825,32.9 28.082,33.149 75.275,33.2 5.107,33.474 62.625,34.025 19.682,34.399 111.4,35 7.65,35.05 1.775,35.075 102,35.15 98.075,35.8 17.644,36.526 25.609,36.54 21.957,37.249 114.102,37.651 27.782,37.699 32.999,37.971 46.925,38.625 100.15,38.775 29.373,39.028 95.975,39.05 28.375,39.075 93.025,39.1 21,39.5 51.075,39.5 29.373,39.903 28.375,39.95 77.225,40.6 34.1,40.675 80.8,40.675 20.119,41.633 95.975,41.725 17.95,41.825 13,42 16,42.125 4.582,42.774 8.157,42.824 1.725,42.875 114.002,42.901 47.925,42.925 62.775,43.05 64.1,43.05 17.95,43.125 20.125,43.125 16.775,43.2 77.2,43.3 14.6,43.525 34.05,43.925 110.8,44.175 31,44.3 73.5,44.3 15.6,44.375 27.65,44.375 24.9,44.45 22.45,44.475 100.925,44.675 62.775,44.7 19.675,44.825 13.25,44.85 6.407,44.874 76.45,45.45 81.875,45.5 66.275,45.575 113.977,45.576 14.3,45.675 103.175,45.775 34.025,45.975 112.007,46.049 29.3,46.15 23.8,46.175 11.9,46.2 1.775,46.35 108.65,46.9 2.74,46.918 5.5,46.925 8.075,46.925 3.525,46.975 6.79,46.968 0.915,46.993 12.975,47 1.915,47.043 22.225,47.25 25.725,47.425 11.65,47.5 4.465,47.543 30.9,47.675 42.875,47.75 8.715,47.893 114.002,47.976 14,48 39.375,48.025 36.675,48.1 80.75,48.15 84.15,48.175 12.95,48.2 93.724,48.586 13.548,48.753 8.725,48.8 63.432,48.924 57.633,49.118 104.375,49.1 108.375,49.15 111.207,49.149 12.95,49.45 66.575,49.475 11.625,49.55 67.929,49.533 61.232,49.69 59.65,49.75 36.4,49.95 33.975,50.5 113.977,50.551 93,50.9 100.875,51.025 71.75,51.075 21.6,51.2 20.357,51.249 12.95,51.3 78.4,51.375 41.207,51.399 101.75,51.534 73.425,51.725 26.475,51.8 109.15,52.225 31.9,52.275 22.75,52.475 28.1,52.55 113.927,53.426 67.8,53.475 18.757,54.672 18.492,55.167 34.9,55.2 32.2,55.3 47.5,55.3 52.5,55.3 25.382,55.424 18.17,55.635 96.6,56.325 8.74,56.468 8.565,57.318 104,57.5 3.615,57.518 4.565,57.543 5.54,57.743 6.54,57.993 1.19,58.043 3.14,58.093 2.244,58.175 7.911,58.172 103.652,58.876 106.477,58.901 109.152,58.901 1.177,59.001 5.177,59.001 89.202,58.976 9.327,59.026 86.802,59.026 22.1,59.05 35.052,59.051 88.05,59.05 13.352,59.076 17.927,59.076 26.475,59.075 52.602,59.076 71.627,59.076 30.077,59.101 57.575,59.1 62.5,59.1 67.827,59.101 39.725,59.125 44.875,59.125 48.877,59.126
JS_A: R125.2 SW105.1 | length 1.5
  Top Layer w0.1: SW105.1@88.57,5.464 89.612,4.423 R125.2@89.612,4.412
JS_B: R126.2 SW105.3 | length 1.7
  Top Layer w0.1: SW105.3@90.586,7.48 91.253,6.812 R126.2@92.012,6.812
JS_C: R127.2 SW105.6 | length 1.6
  Top Layer w0.1: R127.2@84.612,13.712 85.53,12.795 SW105.6@85.53,12.536
JS_CEN: R113.2 SW105.2 | length 1.7
  Top Layer w0.1: SW105.2@89.578,6.472 89.618,6.472 90.14,5.95 90.701,5.95 R113.2@90.978,5.673
JS_D: R124.2 SW105.4 | length 1.6
  Top Layer w0.1: R124.2@82.612,11.712 83.514,10.81 SW105.4@83.514,10.52
LED_JLINK: LED901.2 TPJ912.1 U900.A7 | length 52.3
  Top Layer w0.1: v1(46.425,38.275) 46.425,38.864 46.643,39.082 46.643,40.09 46.525,40.208 46.525,40.575 46.6,40.65 U900.A7@46.6,41.5
  Top Layer w0.2: v1(15.051,50.534) 15.051,49.826 LED901.2@15.075,49.85 ; LED901.2@15.075,49.85 15.205,49.98 15.2,49.98 15.075,49.855 LED901.2@15.075,49.85
  Signal Layer 3 w0.1: v1@15.057,50.527 16.875,48.709 16.875,45.625 21.525,40.975 25.846,40.975 26.321,41.45 31.125,41.45 33.775,38.8 41.075,38.8 41.875,39.6 43.225,39.6 44.64,38.185 45.135,38.185 45.175,38.225 46.375,38.225 v1(46.425,38.275)
  Bottom Layer w0.1: v1(46.425,38.275) 46.425,38.75 46.775,39.1 48.35,39.1 48.925,38.525 48.925,36.051 TPJ912.1@50.751,34.225
LED_STATUS_G: LED904.3 U900.D13 | length 30.9
  Top Layer w0.1: v1(41.225,42.45) 41.25,42.475 41.8,42.475 42.325,43 U900.D13@43.6,43
  Top Layer w0.2: LED904.3@21.15,49.75 v1(21.85,49.75)
  Signal Layer 3 w0.1: v1(21.85,49.75) 20.3,48.2 20.3,45.525 20.8,45.025 35.525,45.025 38.668,41.882 39.807,41.882 40.3,42.375 41.175,42.375 41.175,42.4 v1(41.225,42.45)
LED_STATUS_R: LED904.4 U900.E13 | length 28.7
  Top Layer w0.1: v1(39.304,43.07) 39.304,43.018 39.671,42.65 40.575,42.65 40.968,43.043 41.768,43.043 42.225,43.5 U900.E13@43.6,43.5
  Top Layer w0.2: LED904.4@21.15,49.05 v1(21.85,49.05)
  Signal Layer 3 w0.1: v1(21.85,49.05) 20.85,48.05 20.85,45.95 21.325,45.475 35.683,45.475 38.087,43.07 v1(39.304,43.07)
MCU_P0.0: J102.6 R300.1 U1.6 | length 82
  Top Layer w0.1: v1(79.3,35.575) 78.975,35.25 R300.1@78.975,35 79.75,34.225 79.9,34.225 80.975,33.15 U1.6@81.975,33.15
  Signal Layer 3 w0.1: J102.6@36.03,56.602 36.03,56.73 37.9,58.6 85.625,58.6 v1(85.975,58.25)
  Signal Layer 4 w0.1: v1(79.3,35.575) 78.9,35.975 78.9,49.8 83.275,54.175 83.275,56.85 84.675,58.25 v1(85.975,58.25)
MCU_P0.2: C102.1 J102.10 R100.1 SW100.3 SW100.4 TPJ652.1 U1.4 U950.8 | length 154.3
  Top Layer w0.1: C102.1@50.45,11.725 50.975,11.725 R100.1@51,11.7 51.225,11.925 SW100.3@51.925,11.925 SW100.4@56.075,11.925 56.194,12.044 v1(56.956,12.044) ; v1(52.083,44.246) 52.194,44.246 U950.8@52.425,44.015 ; v1(80.425,35.125) 80.425,34.475 80.75,34.15 U1.4@81.975,34.15
  Signal Layer 3 w0.1: J102.10@41.11,56.602 41.11,56.71 42.8,58.4 85.2,58.4 v1(85.975,57.625) ; v1(62.5,16.5) 62.531,16.469 67.169,16.469 74.65,23.95 75.731,23.95 77.882,26.101 78.132,26.101 78.9,26.869 78.9,33.125 80.425,34.65 v1(80.425,35.125)
  Signal Layer 4 w0.1: v1(52.083,44.246) 53.654,42.675 53.654,41.921 54.475,41.1 54.475,37.425 55.693,36.207 55.693,16.893 55.025,16.225 55.025,13.975 v1(56.956,12.044) ; v1(80.425,35.125) 79.1,36.45 79.1,49.675 83.475,54.05 83.475,56.65 84.85,58.025 85.575,58.025 v1(85.975,57.625)
  Bottom Layer w0.1: v1(56.956,12.044) 56.985,12.015 57.216,12.015 57.421,12.221 TPJ652.1@61.303,16.102 62.102,16.102 v1(62.5,16.5)
MCU_P0.3: C103.1 J102.12 R101.1 SW101.3 SW101.4 TPJ653.1 U1.3 U950.11 | length 107.1
  Top Layer w0.1: R101.1@38.404,11.758 R101.1@38.429,11.733 38.441,11.745 38.97,11.745 C103.1@38.975,11.75 ; C103.1@38.986,11.756 39.206,11.756 39.375,11.925 SW101.3@39.925,11.925 SW101.4@44.075,11.925 v1(45.075,11.925) ; U950.11@53.625,44.015 53.625,43.318 54.062,42.881 54.062,42.406 v1(54.047,42.39) ; v1(80.85,34.675) 80.875,34.65 U1.3@81.975,34.65
  Signal Layer 3 w0.1: v1(51.05,16.1) 55.524,16.1 v1(55.544,16.08) 61.681,16.08 61.786,15.975 62.531,15.975 62.964,15.975 66.586,15.975 67.069,15.975 74.844,23.75 75.814,23.75 77.965,25.901 78.215,25.901 79.125,26.812 79.125,32.95 v1(80.85,34.675)
  Signal Layer 4 w0.1: J102.12@43.65,56.602 44.975,55.277 44.975,53.475 47.25,51.2 47.25,48.144 48.212,47.182 50.338,47.182 50.499,47.343 51.007,47.343 51.625,46.725 51.625,46.475 52.7,45.4 52.7,44.254 54.089,42.865 54.089,42.432 v1(54.047,42.39) ; v1(45.075,11.925) 49.25,16.1 v1(51.05,16.1) ; v1@54.062,42.405 54.086,42.382 54.086,41.86 54.725,41.221 54.725,37.525 55.893,36.357 55.893,16.429 v1(55.544,16.08)
  Bottom Layer w0.1: v1(51.05,16.1) 51.052,16.102 TPJ653.1@51.953,16.102
MCU_P0.4: J102.14 U1.2 U812.2 | length 90.1
  Top Layer w0.1: v1(66.65,28.5) 66.625,28.5 66.7,28.575 U812.2@66.7,29.165 ; v1(79.9,36.425) 81.175,35.15 U1.2@81.975,35.15
  Signal Layer 3 w0.1: J102.14@46.19,56.602 47.788,58.2 84.775,58.2 85.368,57.607 v1(85.368,57.6) ; v1(66.65,28.5) 66.65,27.4 67.25,26.8 68.075,26.8 68.668,26.207 70.063,26.207 70.348,26.492 74.492,26.492 75.775,27.775 75.775,31.875 78.025,34.125 78.025,35.85 78.6,36.425 v1(79.9,36.425)
  Signal Layer 4 w0.1: v1(79.9,36.425) 79.3,37.025 79.3,49.533 83.675,53.908 83.675,56.375 84.9,57.6 v1(85.368,57.6)
MCU_P0.5: J102.16 U1.1 U812.4 | length 86.9
  Top Layer w0.1: U812.4@67.5,29.165 67.5,28.5 67.564,28.436 68.147,28.436 v1(68.207,28.496) ; v1(79.775,37.125) 81.25,35.65 U1.1@81.975,35.65
  Signal Layer 3 w0.1: J102.16@48.73,56.602 50.128,58 84.408,58 86.083,56.325 v1(86.425,56.325) ; v1(68.207,28.496) 68.284,28.419 69.075,28.419 69.797,27.697 70.117,27.697 71.122,26.692 74.409,26.692 75.55,27.833 75.55,31.95 77.825,34.225 77.825,36.225 78.725,37.125 v1(79.775,37.125)
  Signal Layer 4 w0.1: v1(79.775,37.125) 79.5,37.4 79.5,49.45 83.875,53.825 83.875,55.925 84.275,56.325 v1(86.425,56.325)
MCU_P1.4: J102.27 R301.1 U1.42 | length 44.7
  Top Layer w0.1: R301.1@83.45,39.8 v1(83.45,40.45) ; U1.42@86.425,37.1 86.429,37.104 86.429,38.079 v1(86.475,38.125)
  Signal Layer 3 w0.1: J102.27@63.97,54.062 63.996,54.062 65.051,53.007 69.974,53.007 71.28,54.312 85.437,54.312 85.75,54.625 v1(85.75,54.925)
  Signal Layer 4 w0.1: v1(85.75,54.925) 85.75,48.592 83.45,46.292 v1(83.45,40.45) 83.45,39.85 84.45,38.85 85.75,38.85 v1(86.475,38.125)
MCU_P1.5: J102.25 R5.1 | length 41.4
  Top Layer w0.1: v1(84.65,45.525) 85.425,45.525 86.925,44.025 R5.1@86.925,41.65
  Signal Layer 3 w0.1: J102.25@61.43,54.062 62.685,52.807 70.057,52.807 71.341,54.091 85.666,54.091 86.025,54.45 86.275,54.7 86.347,54.7 v1(86.347,54.713)
  Signal Layer 4 w0.1: v1(84.65,45.525) 84.65,47.1 86,48.45 86,54.367 v1(86.347,54.713)
MCU_P1.6: J102.23 R135.2 U1.40 | length 90.8
  Top Layer w0.1: v1(69.689,16.436) 69.689,13.661 R135.2@69.8,13.55 ; U1.40@87.425,37.1 87.425,37.75 88.2,38.525 88.975,38.525 v1(89.825,39.375)
  Signal Layer 3 w0.1: v1(69.689,16.436) 69.689,17.339 75.275,22.925 79.25,22.925 80.3,23.975 v1(80.3,24.4)
  Signal Layer 4 w0.1: v1(80.3,24.4) 81.118,23.582 87.007,23.582 89.75,26.325 89.75,37.75 89.25,38.25 89.25,38.8 v1(89.825,39.375) 90.175,39.725 90.175,46.325 87.375,49.125 87.375,52.625 87.45,52.7 v1(87.453,52.697)
  Bottom Layer w0.1: J102.23@58.89,54.062 59.984,52.968 70.193,52.968 71.7,54.475 82.2,54.475 83.975,52.7 87.45,52.7 v1(87.453,52.697)
MCU_P1.7: J102.21 R136.2 U1.39 | length 88.3
  Top Layer w0.1: v1(68.925,16.025) 68.944,16.006 R136.2@68.944,15.184 ; U1.39@87.925,37.1 87.925,37.875 88.3,38.25 89.4,38.25 89.8,38.65 v1(89.822,38.65)
  Signal Layer 3 w0.1: v1(68.925,16.025) 68.925,16.875 75.175,23.125 78.811,23.125 v1(79.71,24.024)
  Signal Layer 4 w0.1: v1(79.71,24.024) 80.353,23.382 87.132,23.382 90.025,26.275 90.025,38.336 89.819,38.543 v1@89.819,38.647 ; v1(87.775,49.5) 90.4,46.875 90.4,39.25 89.822,38.672 v1(89.822,38.65)
  Bottom Layer w0.1: J102.21@56.35,54.062 57.644,52.768 71.732,52.768 75.175,49.325 86.55,49.325 86.725,49.5 v1(87.775,49.5)
MCU_P2.0: J102.19 R137.2 U1.38 | length 96.6
  Top Layer w0.1: R137.2@68.052,15.187 68.052,16.002 v1(68.075,16.025) ; U1.38@88.425,37.1 88.425,37.8 88.675,38.05 89.9,38.05 v1(90.425,38.575)
  Signal Layer 3 w0.1: v1(68.075,16.025) 68.075,16.375 75.05,23.35 77.325,23.35 78.15,24.175 78.15,25.375 v1(78.147,25.378) ; v1(78.4,40.45) 80.05,40.45 80.775,39.725 83.375,39.725 84.307,38.793 86.407,38.793 87.2,38 89.85,38 v1(90.425,38.575)
  Signal Layer 4 w0.1: v1(78.147,25.378) 78.15,25.378 78.15,25.486 78.575,25.911 78.575,33.775 78.075,34.275 78.075,36.225 78.65,36.8 78.65,40.2 v1(78.4,40.45) ; v1(88.55,49.482) 88.55,49.297 88.55,49.108 90.625,47.033 90.625,38.775 v1(90.425,38.575)
  Bottom Layer w0.1: J102.19@53.81,54.062 55.304,52.568 71.632,52.568 75.1,49.1 88.15,49.1 88.532,49.482 v1(88.55,49.482)
MCU_P2.3: J102.13 U1.35 | length 64.5
  Top Layer w0.1: U1.35@90.375,35.15 90.825,35.15 v1(91.825,35.15)
  Signal Layer 3 w0.1: J102.13@46.19,54.062 46.269,54.062 47.431,52.9 57.2,52.9 58.875,51.225 60.475,51.225 61.2,51.95 70.631,51.95 72.356,53.675 84.2,53.675 86.775,51.1 88.85,51.1 v1(89.175,50.775)
  Signal Layer 4 w0.1: v1(89.175,50.775) 89.175,50.375 89.175,49.1 91.041,47.234 91.041,35.934 v1(91.825,35.15)
MCU_P2.4: J102.11 U1.34 | length 66.7
  Top Layer w0.1: U1.34@90.375,34.65 91.375,34.65 v1(91.42,34.695)
  Signal Layer 3 w0.1: J102.11@43.65,54.062 43.65,53.9 44.85,52.7 57.075,52.7 58.775,51 60.626,51 61.301,51.675 70.701,51.675 72.501,53.475 84.1,53.475 86.875,50.7 v1(88.525,50.7)
  Signal Layer 4 w0.1: v1(88.525,50.7) 88.95,50.275 88.95,48.991 90.841,47.1 90.841,35.274 v1(91.42,34.695)
MCU_P2.5: C106.1 J102.9 R111.1 SW105.5 U1.33 | length 98.9
  Top Layer w0.1: v1(82.8,13.525) 83.212,13.113 84.522,11.802 SW105.5@84.522,11.528 ; U1.33@90.375,34.15 91.65,34.15 v1(91.672,34.128)
  Signal Layer 3 w0.1: J102.9@41.11,54.062 42.547,52.625 42.672,52.5 56.9,52.5 58.6,50.8 60.709,50.8 61.384,51.475 70.784,51.475 72.534,53.225 84.05,53.225 86.982,50.293 89.468,50.293 v1(89.9,50.725)
  Signal Layer 4 w0.1: v1(82.8,13.525) 90.275,21 90.275,32.725 92.243,34.693 92.243,35.382 91.241,36.384 91.241,47.359 89.525,49.075 89.525,50.35 v1(89.9,50.725)
MCU_P3.4: J101.14 U1.26 | length 60.1
  Top Layer w0.1: U1.26@90.375,30.65 91.394,30.65 91.95,30.65 v1(91.975,30.675)
  Signal Layer 3 w0.1: J101.14@46.19,5.802 48.063,7.675 50.225,7.675 56.95,14.4 69.7,14.4 75.9,20.6 78.823,20.6 81.925,23.702 81.925,27.727 82.723,28.525 88.525,28.525 90.675,30.675 v1(91.975,30.675)
MCU_P3.5: J101.16 U1.25 | length 56.4
  Top Layer w0.1: U1.25@90.375,30.15 v1(91.55,30.15)
  Signal Layer 3 w0.1: J101.16@48.73,5.802 57.103,14.175 69.775,14.175 75.975,20.375 78.881,20.375 82.125,23.619 82.125,27.644 82.806,28.325 88.75,28.325 90.575,30.15 v1(91.55,30.15)
MCU_P3.6: J101.18 U1.24 | length 50.9
  Top Layer w0.1: U1.24@88.925,28.7 88.925,28.1 89.202,27.823 v1(89.202,27.668)
  Signal Layer 3 w0.1: J101.18@51.27,5.802 59.218,13.75 69.959,13.75 75.684,19.475 78.264,19.475 82.325,23.536 82.325,27.561 82.889,28.125 88.725,28.125 89.182,27.668 v1(89.202,27.668)
MCU_P3.7: J101.20 U1.23 | length 47.3
  Top Layer w0.1: U1.23@88.425,28.7 88.398,28.673 88.398,27.752 v1(88.575,27.575)
  Signal Layer 3 w0.1: J101.20@53.81,5.802 61.358,13.35 70.125,13.35 75.825,19.05 78.404,19.05 82.775,23.421 82.775,26.9 83.775,27.9 88.25,27.9 v1(88.575,27.575)
MCU_P4.0: J101.22 U1.22 | length 43.7
  Top Layer w0.1: v1(87.925,27.45) U1.22@87.925,28.7
  Signal Layer 3 w0.1: J101.22@56.35,5.802 62.198,11.65 71.57,11.65 83.2,23.28 83.2,26.2 84.675,27.675 87.7,27.675 v1(87.925,27.45)
MCU_P4.1: J101.24 U1.21 | length 41.5
  Top Layer w0.1: U1.21@87.425,28.7 87.425,27.2 v1(87.8,26.825)
  Signal Layer 3 w0.1: J101.24@58.89,5.802 64.338,11.25 71.736,11.25 83.675,23.189 83.675,25.525 85.575,27.425 87.2,27.425 v1(87.8,26.825)
MCU_P4.2: J101.26 U1.20 | length 37.5
  Top Layer w0.1: U1.20@86.925,28.7 86.925,27.025 v1(86.95,27)
  Signal Layer 3 w0.1: J101.26@61.43,5.802 66.478,10.85 71.901,10.85 84.425,23.374 84.425,25.125 85.05,25.75 85.05,26.5 85.038,26.513 85.525,27 v1(86.95,27)
MCU_P4.3: J101.28 U1.19 | length 34.2
  Top Layer w0.1: v1(86.425,26.35) U1.19@86.425,28.7
  Signal Layer 3 w0.1: J101.28@63.97,5.802 68.618,10.45 72.067,10.45 84.9,23.283 84.9,24.825 v1(86.425,26.35)
MCU_P4.4: J101.27 U1.18 | length 36.2
  Top Layer w0.1: v1(85.925,24.57) U1.18@85.925,28.7
  Signal Layer 3 w0.1: J101.27@63.97,3.262 65.225,4.517 65.225,6.2 69.275,10.25 72.15,10.25 85.925,24.025 v1(85.925,24.57)
MCU_P4.5: J101.25 U1.17 | length 38.3
  Top Layer w0.1: U1.17@85.425,28.7 85.425,26.325 v1(85.45,26.3)
  Signal Layer 3 w0.1: J101.25@61.43,3.262 62.775,4.607 62.775,6.375 67.05,10.65 71.984,10.65 84.675,23.341 84.675,25 85.45,25.775 v1(85.45,26.3)
MCU_P4.6: J101.23 U1.16 | length 40.2
  Top Layer w0.1: v1(84.6,25.893) 84.618,25.893 84.925,26.2 U1.16@84.925,28.7
  Signal Layer 3 w0.1: J101.23@58.89,3.262 60.175,4.547 60.175,6.225 65,11.05 71.819,11.05 84.2,23.431 84.2,25.475 84.6,25.875 v1(84.6,25.893)
MCU_P4.7: J101.21 U1.15 | length 42.4
  Top Layer w0.1: v1(84.41,26.815) 84.41,28.685 U1.15@84.425,28.7
  Signal Layer 3 w0.1: J101.21@56.35,3.262 57.675,4.587 57.675,6.5 62.625,11.45 71.653,11.45 83.45,23.247 83.45,25.856 v1(84.41,26.815)
N17207915: LED2.4 R135.1 | length 0.9
  Top Layer w0.2: LED2.4@68.925,12.575 69.725,12.575 R135.1@69.8,12.65
N17207930: LED2.3 R136.1 | length 0.9
  Top Layer w0.1: LED2.3@68.925,13.425 68.925,14.266 R136.1@68.944,14.284
N17207934: LED2.2 R137.1 | length 0.9
  Top Layer w0.1: R137.1@68.052,14.287 68.075,14.264 LED2.2@68.075,13.425
N17208223: P100.3 R145.1 R146.2 | length 11.7
  Top Layer w0.1: P100.3@46.25,30.175 46.25,29.625 46.775,29.1 46.775,28.475 48,27.25 49.15,27.25 50.175,28.275 50.175,28.875 50.372,29.072 50.428,29.072 53.817,29.072 R145.1@54.007,28.882 54.012,28.877 54.872,28.877 R146.2@54.877,28.872
N17208307: P100.10 TP150.1 U100.16 | length 14.7
  Top Layer w0.1: v1(39.304,31.944) 39.431,31.944 39.79,31.585 U100.16@39.79,31.375 ; v1(49.75,29.125) P100.10@49.75,30.175
  Signal Layer 3 w0.1: v1(39.304,31.944) 39.279,31.919 40.023,31.175 41.985,31.175 42.423,30.738 43.385,29.775 49.1,29.775 v1(49.75,29.125)
  Bottom Layer w0.1: TP150.1@38.3,32.3 38.544,32.3 38.9,31.944 39.254,31.944 v1(39.304,31.944)
N17208309: P100.9 TP151.1 U100.4 | length 14.8
  Top Layer w0.1: v1(39.492,27.925) 39.492,29.525 39.542,29.575 U100.4@39.59,29.575 ; v1(49.25,28.25) P100.9@49.25,30.175
  Signal Layer 3 w0.1: v1(39.492,27.925) 40.818,27.925 40.918,28.025 42.15,28.025 48.325,28.025 48.55,28.25 v1(49.25,28.25)
  Bottom Layer w0.1: TP151.1@38.3,27.8 38.362,27.862 39.43,27.862 v1(39.492,27.925)
N17208311: P100.8 TP152.1 U100.8 | length 12.3
  Top Layer w0.1: U100.8@40.99,28.975 40.99,28.21 41.531,27.669 v1(41.531,27.63) ; v1(48.75,27.725) P100.8@48.75,30.175
  Signal Layer 3 w0.1: v1(41.531,27.63) 41.576,27.675 v1@48.75,27.675
  Bottom Layer w0.1: TP152.1@40.8,28.4 40.8,28.38 41.531,27.65 v1(41.531,27.63)
N17208347: P100.7 TP153.1 | length 2.8
  Top Layer w0.1: v1(48,28.711) 48,28.818 48.25,29.068 P100.7@48.25,30.175
  Bottom Layer w0.1: TP153.1@47.8,27.6 47.8,28.5 48,28.7 v1(48,28.711)
N17209732: R104.1 SW100.1 SW100.2 | length 5.2
  Top Layer w0.1: R104.1@50.847,14.12 51.88,14.12 SW100.1@51.925,14.075 52.193,14.075 SW100.2@56.075,14.075
N17209791: R105.1 SW101.1 SW101.2 | length 5.4
  Top Layer w0.1: R105.1@38.8,14.175 38.865,14.11 39.89,14.11 SW101.1@39.925,14.075 ; SW101.1@39.9,14.05 SW101.1@39.925,14.075 ; SW101.2@44.075,14.075 SW101.1@39.925,14.075
N17247543: R7.2 SW1.3 SW1.4 | length 5.6
  Top Layer w0.1: SW1.3@104.925,11.925 109.075,11.925 110.1,11.925 110.4,12.225 R7.2@110.375,12.25
N17576293: R700.1 U701.7 | length 1
  Top Layer w0.2: U701.7@32.375,30.125 32.375,29.473 32.627,29.221 R700.1@32.627,29.211
N17576321: R702.1 R703.2 U701.5 | length 2.4
  Top Layer w0.2: R703.2@30.1,30.125 U701.5@31.375,30.125 31.375,29.18 R702.1@31.216,29.021
N17576325: C705.1 U701.6 | length 1
  Top Layer w0.2: U701.6@31.875,30.125 31.875,29.374 32.05,29.199 C705.1@32.05,29.179
N17576365: R707.2 TP713.1 U702.3 | length 2.9
  Top Layer w0.1: U702.3@43.585,36.675 44.458,36.675 R707.2@44.523,36.739 44.638,36.624 v1(45.104,36.624)
  Bottom Layer w0.1: TP713.1@43.8,36.7 43.838,36.662 45.065,36.662 v1(45.104,36.624)
N17576367: R706.2 TP712.1 U702.8 | length 2.8
  Top Layer w0.1: v1(40.35,38.194) 40.42,38.124 40.42,37.959 40.5,37.878 R706.2@40.855,37.878 ; R706.2@40.87,37.894 R706.2@40.855,37.878 ; U702.8@41.815,37.475 41.289,37.475 40.885,37.878 R706.2@40.855,37.878
  Bottom Layer w0.1: TP712.1@39.7,38.8 39.722,38.8 40.328,38.194 v1(40.35,38.194)
N17576373: R705.2 TP711.1 U702.11 | length 4.1
  Top Layer w0.1: v1(39.421,35.535) 39.452,35.566 39.452,35.939 R705.2@39.993,36.479 40.213,36.259 41.799,36.259 U702.11@41.815,36.275
  Bottom Layer w0.1: v1(39.421,35.535) 39.421,35.424 39.528,35.318 39.528,34.872 TP711.1@39.7,34.7
N17576375: R708.2 TP714.1 U702.1 | length 2.8
  Top Layer w0.1: v1(43.625,35.475) 43.625,35.5 43.585,35.54 U702.1@43.585,35.875 44.3,35.875 R708.2@44.4,35.775
  Bottom Layer w0.1: TP714.1@43.2,34.1 43.2,35.05 v1(43.625,35.475)
N17576435: C707.1 L702.2 U702.14 | length 1.9
  Top Layer w0.2: C707.1@42.85,34.975 42.9,35.025 U702.14@42.9,35.79
  Top Layer w0.3: L702.2@42.435,34.05 42.85,34.465 C707.1@42.85,34.975
N17581506: R808.1 U802.6 U802.12 U806.5 U806.6 U806.12 U806.13 U807.3 | length 24.8
  Top Layer w0.1: v1(69.9,26.6) 69.95,26.55 R808.1@70.475,26.55 71.038,26.55 U807.3@71.063,26.525 ; U806.6@69.9,35.8 69.9,36.275 69.975,36.35 70.25,36.35 ; U802.6@69.9,40.3 69.912,40.312 69.912,40.912 v1(69.975,40.975) ; U806.5@70.4,35.8 70.4,36.2 70.25,36.35 ; U806.12@71.4,33.4 71.4,32.835 71.5,32.735 v1(71.5,32.625) ; U802.12@71.4,37.9 71.4,37.275 v1(71.275,37.15) 70.669,37.15 70.25,36.731 70.25,36.35 ; v1@71.5,32.575 71.9,32.975 U806.13@71.9,33.4
  Signal Layer 3 w0.1: v1(71.275,37.15) v1@71.35,37.15
  Signal Layer 4 w0.1: v1(69.9,26.6) 69.925,26.625 70.3,26.625 70.925,27.25 70.925,28.125 71.5,28.7 v1(71.5,32.625) 71.5,34.45 70.25,35.7 70.25,36.8 70.6,37.15 v1(71.275,37.15) 71.275,39.675 v1(69.975,40.975)
N17581518: C804.1 C810.1 L801.2 U804.A2 U809.A2 | length 9.7
  Top Layer w0.2: U804.A2@51.325,37.4 51.325,37.15 51.825,36.65 C804.1@51.9,36.65 53.6,36.65 v1(53.65,36.7) ; v1(51.5,40.3) C810.1@52.025,40.3 52.05,40.325 U809.A2@52.05,40.925
  Top Layer w0.3: v1(53.65,36.7) L801.2@53.65,37.3
  Signal Layer 4 w0.25: 51.5,39.8 51.55,39.75 51.55,39.375 51.6,39.325
  Signal Layer 4 w0.3: 51.5,39.8 v1(51.5,40.3) ; 51.6,39.325 51.9,39.025 51.9,37.325 52.525,36.7 v1(53.65,36.7)
N17581544: Q800.1 U806.10 | length 9.8
  Top Layer w0.1: Q800.1@68.325,37.95 68.334,37.959 68.334,38.609 v1(68.347,38.622) ; v1(69.15,32.175) 69.425,32.175 70.4,33.15 U806.10@70.4,33.4
  Signal Layer 4 w0.1: v1(68.347,38.622) 68.347,38.597 67.925,38.175 67.925,33.206 68.956,32.175 v1(69.15,32.175)
N17581639: RP801.5 U808.21 | length 1.1
  Top Layer w0.1: U808.21@65.195,44.3 RP801.5@66.25,44.3
N17581641: RP801.6 U808.20 | length 1.1
  Top Layer w0.1: U808.20@65.195,43.8 RP801.6@66.25,43.8
N17581645: RP801.7 U808.19 | length 1.1
  Top Layer w0.1: U808.19@65.195,43.3 RP801.7@66.25,43.3
N17581647: RP801.8 U808.18 | length 1.1
  Top Layer w0.1: U808.18@65.195,42.8 RP801.8@66.25,42.8
N17581665: R805.1 U808.17 | length 1.3
  Top Layer w0.1: U808.17@65.195,42.3 66.05,42.3 R805.1@66.4,41.95
N17581692: RP800.8 U809.C1 | length 3.8
  Top Layer w0.1: U809.C1@52.55,41.925 52.555,41.92 52.958,41.92 v1(52.964,41.914) ; v1(53.525,39.65) RP800.8@54.1,39.65
  Signal Layer 4 w0.1: v1(52.964,41.914) 53.918,40.96 53.918,40.043 v1(53.525,39.65)
N17581696: RP800.6 U809.C2 | length 4.4
  Top Layer w0.1: v1(51.546,42.505) 51.546,42.464 52.05,41.96 U809.C2@52.05,41.925 ; v1(53.525,40.65) RP800.6@54.1,40.65
  Signal Layer 4 w0.1: v1(51.546,42.505) 52.45,41.601 52.45,41.15 52.95,40.65 v1(53.525,40.65)
N17581702: RP800.5 U804.C1 | length 4.2
  Top Layer w0.1: U804.C1@51.825,38.4 52.125,38.4 53.125,39.4 53.125,40.8 53.132,40.807 53.132,40.813 53.362,41.043 53.993,41.043 RP800.5@54.1,41.15
N17581869: U805.10 U806.9 | length 13
  Top Layer w0.1: U805.10@64.775,37.955 64.775,38.55 64.997,38.772 v1(64.997,38.778) ; v1(69.425,32.8) 69.9,33.275 U806.9@69.9,33.4
  Bottom Layer w0.1: v1(64.997,38.778) 64.997,38.772 64.2,37.975 64.2,36.2 63.75,35.75 63.75,34.3 65.25,32.8 v1(69.425,32.8)
N17581871: U805.9 U806.3 | length 8.1
  Top Layer w0.1: U805.9@65.175,37.955 65.175,38.25 65.4,38.475 65.975,38.475 v1(66.05,38.4) ; v1(71.275,36.5) 71.4,36.375 U806.3@71.4,35.8
  Signal Layer 3 w0.1: v1(66.05,38.4) 66.55,37.9 69.881,37.9 71.275,36.506 v1(71.275,36.5)
N17581873: U802.10 U805.4 | length 6.7
  Top Layer w0.1: U805.4@65.175,36.185 65.175,35.925 65.195,35.925 65.325,35.795 65.325,35.783 65.596,35.512 v1(65.778,35.512) ; v1(68.775,37.3) 68.875,37.4 69.776,37.4 70.024,37.4 70.4,37.776 U802.10@70.4,37.9
  Bottom Layer w0.1: v1(65.778,35.512) 65.837,35.512 67.625,37.3 v1(68.775,37.3)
